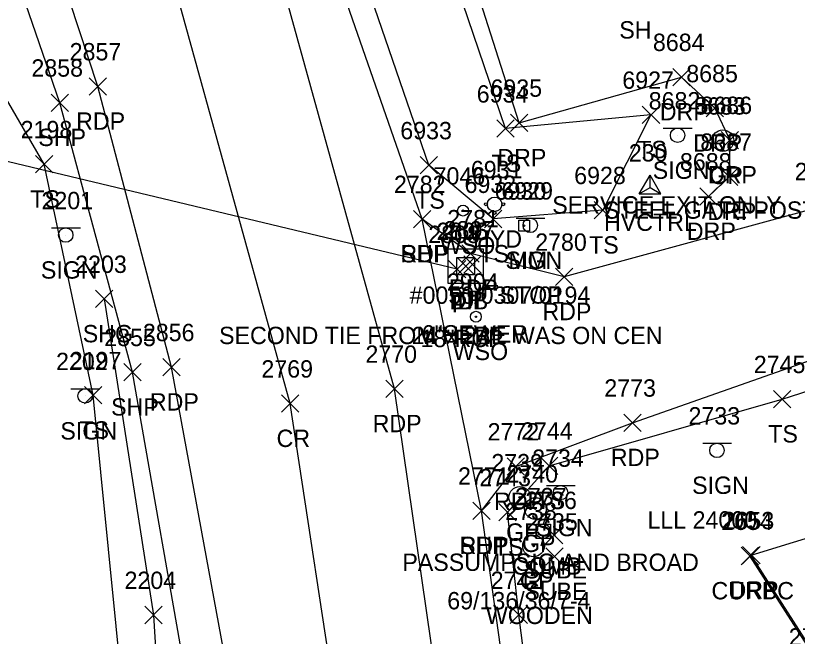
# Model space of a CAD drawing. Extents: x 1769141 to 1770911, y 735471 to 741449.
# Drawn here: x 1770593.8 to 1770683.9, y 737149.7 to 737221.2 of the extents above; entities that cross this region are included whole.
import ezdxf

# ---------------------------------------------------------------- set-up
doc = ezdxf.new("R2010")
doc.units = 0
for name, color, linetype in [('C_A', 7, 'Continuous'), ('C_I', 7, 'Continuous'), ('CPSM', 7, 'Continuous'), ('D_A', 7, 'Continuous'), ('D_C', 7, 'Continuous'), ('D_I', 7, 'Continuous'), ('D_TIC', 7, 'Continuous'), ('DCP', 7, 'Continuous'), ('DS', 7, 'Continuous'), ('L_A', 7, 'Continuous'), ('L_I', 7, 'Continuous'), ('L_TIC', 7, 'Continuous'), ('LELB', 7, 'Continuous'), ('P_A', 7, 'Continuous'), ('P_I', 7, 'Continuous'), ('P_TIC', 7, 'Continuous'), ('PET', 7, 'Continuous'), ('PRC', 7, 'Continuous'), ('PSP', 7, 'Continuous'), ('PSU', 7, 'Continuous'), ('R_A', 7, 'Continuous'), ('R_C', 7, 'Continuous'), ('R_I', 7, 'Continuous'), ('R_TIC', 7, 'Continuous'), ('RC', 7, 'Continuous'), ('RDP', 7, 'Continuous'), ('RGP', 7, 'Continuous'), ('S_A', 7, 'Continuous'), ('S_C', 7, 'Continuous'), ('S_I', 7, 'Continuous'), ('SRM', 7, 'Continuous'), ('SSGN', 7, 'Continuous'), ('U_A', 7, 'Continuous'), ('U_C', 7, 'Continuous'), ('U_I', 7, 'Continuous'), ('U_TIC', 7, 'Continuous'), ('UP', 7, 'Continuous'), ('UWFH', 7, 'Continuous'), ('UWV', 7, 'Continuous')]:
    doc.layers.add(name, color=color, linetype=linetype)

msp = doc.modelspace()

# ---------------------------------------------------------------- linework, layer by layer
at = {"layer": 'CPSM'}
for p, q in [((1770665.701, 737200.682), (1770666.951, 737202.847)), ((1770668.201, 737200.682), (1770666.951, 737202.847)), ((1770666.951, 737201.403), (1770666.951, 737202.847)), ((1770665.701, 737200.682), (1770666.951, 737201.403)), ((1770666.951, 737201.403), (1770666.951, 737201.403)), ((1770666.951, 737201.403), (1770668.201, 737200.682)), ((1770665.701, 737200.682), (1770668.201, 737200.682))]:
    msp.add_line(p, q, dxfattribs=at)
at = {"layer": 'D_TIC'}
for points in [[(1770644.731, 737191.354), (1770646.731, 737193.354)], [(1770646.731, 737191.354), (1770644.731, 737193.354)], [(1770645.493, 737191.533), (1770647.493, 737193.533)], [(1770647.493, 737191.533), (1770645.493, 737193.533)], [(1770643.721, 737191.004), (1770645.721, 737193.004)], [(1770645.721, 737191.004), (1770643.721, 737193.004)]]:
    msp.add_lwpolyline(points, dxfattribs=at)
at = {"layer": 'DCP'}
msp.add_lwpolyline([(1770644.721, 737192.004), (1770575.14, 737208.644)], dxfattribs=at)
at = {"layer": 'DS'}
for p, q in [((1770643.694, 737194.347), (1770647.694, 737194.347)), ((1770643.694, 737190.347), (1770643.694, 737194.347)), ((1770647.694, 737194.347), (1770647.694, 737190.347)), ((1770644.694, 737191.347), (1770644.694, 737193.347)), ((1770644.694, 737193.347), (1770646.694, 737193.347)), ((1770646.694, 737193.347), (1770646.694, 737191.347)), ((1770645.699, 737192.349), (1770645.699, 737192.349)), ((1770645.699, 737192.349), (1770645.699, 737192.349)), ((1770646.694, 737191.347), (1770644.694, 737191.347)), ((1770647.694, 737190.347), (1770643.694, 737190.347))]:
    msp.add_line(p, q, dxfattribs=at)
at = {"layer": 'L_TIC'}
for points in [[(1770666.059, 737208.784), (1770668.059, 737210.784)], [(1770668.059, 737208.784), (1770666.059, 737210.784)], [(1770666.059, 737208.784), (1770668.059, 737210.784)], [(1770668.059, 737208.784), (1770666.059, 737210.784)], [(1770649.276, 737207.194), (1770651.276, 737209.194)], [(1770651.276, 737207.194), (1770649.276, 737209.194)], [(1770596.087, 737203.083), (1770598.087, 737205.083)], [(1770598.087, 737203.083), (1770596.087, 737205.083)], [(1770640.464, 737202.965), (1770642.464, 737204.965)], [(1770642.464, 737202.965), (1770640.464, 737204.965)], [(1770660.511, 737197.795), (1770662.511, 737199.795)], [(1770662.511, 737197.795), (1770660.511, 737199.795)], [(1770647.869, 737196.776), (1770649.869, 737198.776)], [(1770649.869, 737196.776), (1770647.869, 737198.776)], [(1770601.747, 737176.456), (1770603.747, 737178.456)], [(1770603.747, 737176.456), (1770601.747, 737178.456)], [(1770681.17, 737176.009), (1770683.17, 737178.009)], [(1770683.17, 737176.009), (1770681.17, 737178.009)], [(1770654.338, 737168.333), (1770656.338, 737170.333)], [(1770656.338, 737168.333), (1770654.338, 737170.333)], [(1770649.53, 737162.97), (1770651.53, 737164.97)], [(1770651.53, 737162.97), (1770649.53, 737164.97)], [(1770650.841, 737151.128), (1770652.841, 737153.128)], [(1770652.841, 737151.128), (1770650.841, 737153.128)]]:
    msp.add_lwpolyline(points, dxfattribs=at)
at = {"layer": 'LELB'}
for points in [[(1770667.059, 737209.784), (1770650.276, 737208.194), (1770639.804, 737239.076), (1770626.588, 737278.985), (1770615.665, 737316.741), (1770606.889, 737344.413), (1770623.935, 737352.443), (1770627.12, 737356.412), (1770639.628, 737361.755)], [(1770667.059, 737209.784), (1770661.511, 737198.795), (1770648.869, 737197.776), (1770641.464, 737203.965), (1770629.375, 737239.096), (1770618.324, 737274.713), (1770606.199, 737314.017), (1770597.958, 737339.829), (1770601.068, 737347.648), (1770609.076, 737352.74), (1770612.603, 737353.688), (1770612.143, 737354.974), (1770623.018, 737358.017), (1770623.556, 737356.471), (1770626.216, 737360.588)], [(1770527.475, 736899.163), (1770538.393, 736913.827), (1770566.54, 736966.131), (1770583.868, 736999.5), (1770597.778, 737030.524), (1770603.735, 737066.69), (1770606.985, 737105.208), (1770606.274, 737141.963), (1770602.747, 737177.456), (1770597.087, 737204.083), (1770584.307, 737226.172)], [(1770653.31, 737140.571), (1770651.841, 737152.128), (1770650.53, 737163.97), (1770655.338, 737169.333), (1770682.17, 737177.009), (1770704.999, 737184.353), (1770726.776, 737190.276), (1770746.344, 737194.538)]]:
    msp.add_lwpolyline(points, dxfattribs=at)
at = {"layer": 'P_TIC'}
for points in [[(1770602.3, 737212.06), (1770604.3, 737214.06)], [(1770604.3, 737212.06), (1770602.3, 737214.06)], [(1770597.894, 737210.185), (1770599.894, 737212.185)], [(1770599.894, 737210.185), (1770597.894, 737212.185)], [(1770639.683, 737196.771), (1770641.683, 737198.771)], [(1770641.683, 737196.771), (1770639.683, 737198.771)], [(1770639.683, 737196.771), (1770641.683, 737198.771)], [(1770641.683, 737196.771), (1770639.683, 737198.771)], [(1770645.269, 737192.815), (1770647.269, 737194.815)], [(1770647.269, 737192.815), (1770645.269, 737194.815)], [(1770656.056, 737190.112), (1770658.056, 737192.112)], [(1770658.056, 737190.112), (1770656.056, 737192.112)], [(1770603.018, 737187.558), (1770605.018, 737189.558)], [(1770605.018, 737187.558), (1770603.018, 737189.558)], [(1770610.798, 737179.693), (1770612.798, 737181.693)], [(1770612.798, 737179.693), (1770610.798, 737181.693)], [(1770606.285, 737179.121), (1770608.285, 737181.121)], [(1770608.285, 737179.121), (1770606.285, 737181.121)], [(1770636.483, 737177.199), (1770638.483, 737179.199)], [(1770638.483, 737177.199), (1770636.483, 737179.199)], [(1770624.462, 737175.494), (1770626.462, 737177.494)], [(1770626.462, 737175.494), (1770624.462, 737177.494)], [(1770663.939, 737173.295), (1770665.939, 737175.295)], [(1770665.939, 737173.295), (1770663.939, 737175.295)], [(1770650.48, 737168.242), (1770652.48, 737170.242)], [(1770652.48, 737168.242), (1770650.48, 737170.242)], [(1770646.506, 737163.146), (1770648.506, 737165.146)], [(1770648.506, 737163.146), (1770646.506, 737165.146)], [(1770646.506, 737163.146), (1770648.506, 737165.146)], [(1770648.506, 737163.146), (1770646.506, 737165.146)], [(1770608.705, 737151.125), (1770610.705, 737153.125)], [(1770610.705, 737151.125), (1770608.705, 737153.125)]]:
    msp.add_lwpolyline(points, dxfattribs=at)
at = {"layer": 'PET'}
for points in [[(1770273.033, 736558.892), (1770311.785, 736611.417), (1770334.278, 736642.027), (1770362.146, 736677.394), (1770395.214, 736718.715), (1770421.357, 736750.436), (1770447.16, 736781.609), (1770463.211, 736800.129), (1770491.513, 736834.01), (1770534.736, 736889.691), (1770564.339, 736930.522), (1770585.978, 736965.52), (1770596.025, 736985.792), (1770612.398, 737032.331), (1770618.899, 737068.158), (1770621.164, 737108.893), (1770618.696, 737143.125), (1770611.798, 737180.693), (1770603.3, 737213.06), (1770592.485, 737245.879), (1770581.452, 737278.474)], [(1770275.701, 736500.443), (1770293.456, 736523.994), (1770308.246, 736544.527), (1770339.602, 736585.989), (1770354.041, 736607.647), (1770377.094, 736638.846), (1770405.465, 736677.522), (1770433.078, 736714.634), (1770457.829, 736747.118), (1770487.075, 736785.889), (1770511.852, 736818.72), (1770532.144, 736846.484), (1770557.142, 736879.905), (1770576.719, 736906.621), (1770599.363, 736940.91), (1770615.19, 736970.363), (1770629.485, 737005.853), (1770638.546, 737040.65), (1770643.239, 737068.348), (1770645.294, 737100.928), (1770643.286, 737138.022), (1770637.483, 737178.199), (1770623.12, 737230.101), (1770608.302, 737274.144)], [(1770741.957, 737215.362), (1770716.866, 737207.906), (1770686.9, 737199.25), (1770657.056, 737191.112), (1770646.269, 737193.815), (1770640.683, 737197.771)], [(1770647.506, 737164.146), (1770651.48, 737169.242), (1770664.939, 737174.295), (1770687.116, 737182.089), (1770711.527, 737190.661), (1770744.94, 737200.569)]]:
    msp.add_lwpolyline(points, dxfattribs=at)
at = {"layer": 'PRC'}
msp.add_lwpolyline([(1770275.213, 736520.725), (1770298.103, 736551.293), (1770321.863, 736584.275), (1770345.264, 736616.165), (1770366.92, 736646.031), (1770396.691, 736686.202), (1770425.295, 736724.734), (1770448.379, 736754.992), (1770477.139, 736793.691), (1770501.731, 736826.243), (1770522.956, 736854.301), (1770547.637, 736887.359), (1770567.264, 736914.203), (1770589.054, 736947.071), (1770604.648, 736975.905), (1770617.455, 737008.215), (1770626.945, 737043.995), (1770631.179, 737069.881), (1770632.95, 737101.223), (1770631.261, 737138.454), (1770625.462, 737176.494), (1770611.429, 737227.28), (1770596.591, 737271.455)], dxfattribs=at)
at = {"layer": 'PSP'}
for points in [[(1770309.307, 736612.498), (1770333.166, 736643.272), (1770360.374, 736678.088), (1770362.327, 736680.597), (1770393.293, 736720.827), (1770418.703, 736752.623), (1770444.15, 736783.405), (1770460.866, 736802.481), (1770489.604, 736835.53), (1770496.104, 736844.034), (1770495.661, 736846.229), (1770525.964, 736887.568), (1770531.668, 736892.213), (1770561.205, 736933.711), (1770581.742, 736967.46), (1770597.363, 737001.442), (1770607.312, 737032.413), (1770614.05, 737069.489), (1770616.453, 737108.678), (1770613.941, 737142.234), (1770607.285, 737180.121), (1770598.894, 737211.185), (1770587.449, 737244.334), (1770575.082, 737276.146)], [(1770340.145, 736567.061), (1770355.712, 736595.48), (1770384.336, 736632.07), (1770413.376, 736670.654), (1770426.21, 736690.901), (1770435.181, 736712.82), (1770460.126, 736745.306), (1770489.927, 736784.126), (1770514.631, 736816.065), (1770535.698, 736843.486), (1770560.973, 736877.108), (1770581.175, 736903.184), (1770605.599, 736937.839), (1770621.173, 736966.95), (1770635.97, 737003.978), (1770646.024, 737037.66), (1770650.838, 737066.811), (1770652.594, 737098.802), (1770650.922, 737139.651), (1770647.506, 737164.146), (1770640.683, 737197.771), (1770629.066, 737231.113), (1770614.088, 737275.469)]]:
    msp.add_lwpolyline(points, dxfattribs=at)
at = {"layer": 'PSU'}
msp.add_lwpolyline([(1770604.018, 737188.558), (1770609.705, 737152.125), (1770612.634, 737104.121), (1770611.16, 737071.425), (1770604.551, 737041.305), (1770590.598, 736996.499), (1770577.768, 736967.1), (1770561.81, 736939.257), (1770539.537, 736909.195), (1770528.411, 736894.864)], dxfattribs=at)
at = {"layer": 'R_TIC'}
for points in [[(1770669.587, 737213.141), (1770671.587, 737215.141)], [(1770671.587, 737213.141), (1770669.587, 737215.141)], [(1770673.434, 737209.537), (1770675.434, 737211.537)], [(1770675.434, 737209.537), (1770673.434, 737211.537)], [(1770650.862, 737207.862), (1770652.862, 737209.862)], [(1770652.862, 737207.862), (1770650.862, 737209.862)], [(1770675.131, 737205.879), (1770677.131, 737207.879)], [(1770677.131, 737205.879), (1770675.131, 737207.879)], [(1770675.057, 737201.641), (1770677.057, 737203.641)], [(1770677.057, 737201.641), (1770675.057, 737203.641)], [(1770672.702, 737199.369), (1770674.702, 737201.369)], [(1770674.702, 737199.369), (1770672.702, 737201.369)], [(1770677.447, 737157.927), (1770679.447, 737159.927)], [(1770679.447, 737157.927), (1770677.447, 737159.927)], [(1770677.625, 737158.009), (1770679.625, 737160.009)], [(1770679.625, 737158.009), (1770677.625, 737160.009)]]:
    msp.add_lwpolyline(points, dxfattribs=at)
at = {"layer": 'RC'}
msp.add_lwpolyline([(1770653.173, 737139.762), (1770653.711, 737137.452), (1770655.657, 737133.274), (1770657.395, 737130.834), (1770659.771, 737128.379), (1770662.606, 737126.44), (1770665.911, 737125.073), (1770669.989, 737124.148), (1770673.978, 737123.906), (1770678.231, 737124.619), (1770682.006, 737126.195), (1770684.892, 737128.002), (1770688.638, 737131.844), (1770690.645, 737135.217), (1770690.716, 737138.298), (1770689.231, 737142.159), (1770678.447, 737158.927)], dxfattribs=at)
at = {"layer": 'RDP'}
for points in [[(1770651.862, 737208.862), (1770642.081, 737239.565), (1770629.167, 737279.988), (1770617.176, 737317.21), (1770608.974, 737343.703), (1770621.898, 737347.934), (1770627.275, 737353.062), (1770640.145, 737357.787), (1770643.533, 737361.797), (1770642.151, 737367.132), (1770639.052, 737367.799), (1770622.328, 737363.576), (1770608.882, 737359.528), (1770602.841, 737355.207), (1770597.547, 737349.203), (1770594.142, 737341.772)], [(1770651.862, 737208.862), (1770670.587, 737214.141)], [(1770670.587, 737214.141), (1770674.434, 737210.537), (1770676.131, 737206.879), (1770676.057, 737202.641), (1770673.702, 737200.369)], [(1770665.886, 737124.928), (1770669.994, 737124.034), (1770673.956, 737123.824), (1770678.274, 737124.547), (1770682.028, 737126.012), (1770685.086, 737127.999), (1770688.791, 737131.848), (1770690.686, 737135.245), (1770690.957, 737138.391), (1770689.316, 737142.302), (1770678.625, 737159.009), (1770697.636, 737164.852), (1770726.009, 737173.895), (1770752.245, 737179.574)]]:
    msp.add_lwpolyline(points, dxfattribs=at)
at = {"layer": 'RGP'}
for p, q in [((1770675.342, 737206.806), (1770675.342, 737206.806)), ((1770651.924, 737165.688), (1770651.924, 737165.688)), ((1770653.743, 737164.389), (1770653.743, 737164.389)), ((1770653.517, 737160.083), (1770653.517, 737160.083))]:
    msp.add_line(p, q, dxfattribs=at)
for centre, radius in [((1770675.342, 737206.806), 1.25), ((1770675.342, 737206.806), 0.0833), ((1770651.924, 737165.688), 1.25), ((1770651.924, 737165.688), 0.0833), ((1770653.743, 737164.389), 1.25), ((1770653.743, 737164.389), 0.0833), ((1770653.517, 737160.083), 1.25), ((1770653.517, 737160.083), 0.0833)]:
    msp.add_circle(centre, radius, dxfattribs=at)
at = {"layer": 'SRM'}
msp.add_lwpolyline([(1770651.809, 737197.626), (1770653.059, 737197.626), (1770653.059, 737196.376), (1770651.809, 737196.376)], close=True, dxfattribs=at)
msp.add_circle((1770652.434, 737197.001), 0.0833, dxfattribs=at)
at = {"layer": 'SSGN'}
for p, q in [((1770668.475, 737208.257), (1770671.809, 737208.257)), ((1770670.122, 737207.424), (1770670.122, 737207.424)), ((1770651.499, 737197.873), (1770654.832, 737197.873)), ((1770653.145, 737197.039), (1770653.145, 737197.039)), ((1770597.94, 737196.756), (1770601.273, 737196.756)), ((1770599.587, 737195.922), (1770599.587, 737195.922)), ((1770600.186, 737178.208), (1770603.519, 737178.208)), ((1770601.833, 737177.375), (1770601.833, 737177.375)), ((1770673.016, 737171.938), (1770676.349, 737171.938)), ((1770674.663, 737171.105), (1770674.663, 737171.105)), ((1770654.994, 737167.06), (1770658.328, 737167.06)), ((1770656.641, 737166.227), (1770656.641, 737166.227))]:
    msp.add_line(p, q, dxfattribs=at)
for centre in [(1770670.122, 737207.424), (1770653.145, 737197.039), (1770599.587, 737195.922), (1770601.833, 737177.375), (1770674.663, 737171.105), (1770656.641, 737166.227)]:
    msp.add_circle(centre, 0.833, dxfattribs=at)
at = {"layer": 'U_TIC'}
for points in [[(1770654.878, 737160.341), (1770656.878, 737162.341)], [(1770656.878, 737160.341), (1770654.878, 737162.341)], [(1770654.926, 737157.858), (1770656.926, 737159.858)], [(1770656.926, 737157.858), (1770654.926, 737159.858)]]:
    msp.add_lwpolyline(points, dxfattribs=at)
at = {"layer": 'UP'}
for p, q in [((1770654.892, 737163.444), (1770654.642, 737162.61)), ((1770653.809, 737160.944), (1770653.809, 737162.61)), ((1770653.809, 737162.61), (1770655.475, 737162.61)), ((1770655.475, 737162.61), (1770655.475, 737160.944)), ((1770654.642, 737161.777), (1770654.642, 737161.777)), ((1770655.475, 737160.944), (1770653.809, 737160.944)), ((1770654.392, 737160.11), (1770654.642, 737160.944))]:
    msp.add_line(p, q, dxfattribs=at)
msp.add_circle((1770654.642, 737161.777), 0.833, dxfattribs=at)
at = {"layer": 'UWFH'}
msp.add_line((1770649.027, 737199.474), (1770649.027, 737199.474), dxfattribs=at)
for centre, radius in [((1770648.027, 737199.474), 0.167), ((1770649.027, 737199.474), 0.833), ((1770650.027, 737199.474), 0.167), ((1770649.027, 737198.474), 0.167)]:
    msp.add_circle(centre, radius, dxfattribs=at)
at = {"layer": 'UWV'}
for centre, radius in [((1770645.392, 737198.739), 0.625), ((1770645.392, 737198.739), 0.0833), ((1770646.874, 737186.51), 0.625), ((1770646.874, 737186.51), 0.0833)]:
    msp.add_circle(centre, radius, dxfattribs=at)

# ---------------------------------------------------------------- texts
at = {"layer": 'C_A'}
msp.add_text('HVCTRL', height=2, dxfattribs=at).set_placement((1770661.644, 737196.403))
at = {"layer": 'C_I'}
msp.add_text('230', height=2, dxfattribs=at).set_placement((1770664.502, 737204.403))
at = {"layer": 'D_A'}
for s, p in [('DIB', (1770643.834, 737187.354)), ('P', (1770644.099, 737187.004)), ('DI', (1770644.754, 737187.349)), ('P', (1770645.871, 737187.533))]:
    msp.add_text(s, height=2, dxfattribs=at).set_placement(p)
at = {"layer": 'D_C'}
for s, p in [('SECOND TIE FROM HERE WAS ON CEN', (1770617.267, 737183.354)), ('24"x 24"', (1770639.479, 737183.349)), ('6"SEWER', (1770640.627, 737183.533)), ('18"RCP', (1770640.493, 737183.004))]:
    msp.add_text(s, height=2, dxfattribs=at).set_placement(p)
at = {"layer": 'D_I'}
for s, p in [('2808', (1770641.383, 737195.004)), ('2806', (1770642.338, 737195.354)), ('2805', (1770642.361, 737195.349)), ('2807', (1770643.155, 737195.533))]:
    msp.add_text(s, height=2, dxfattribs=at).set_placement(p)
at = {"layer": 'L_A'}
for s, p in [('SH', (1770663.404, 737218.578)), ('TS', (1770665.468, 737204.784)), ('TS', (1770665.468, 737204.784)), ('TS', (1770648.685, 737203.194)), ('TS', (1770595.496, 737199.083)), ('TS', (1770639.874, 737198.965)), ('TS', (1770659.921, 737193.795)), ('TS', (1770647.279, 737192.776)), ('TS', (1770601.156, 737172.456)), ('TS', (1770680.579, 737172.009)), ('TS', (1770653.748, 737164.333)), ('TS', (1770648.94, 737158.97))]:
    msp.add_text(s, height=2, dxfattribs=at).set_placement(p)
at = {"layer": 'L_I'}
for s, p in [('6927', (1770663.752, 737212.784)), ('6927', (1770663.752, 737212.784)), ('6934', (1770646.969, 737211.194)), ('2198', (1770594.394, 737207.083)), ('6933', (1770638.157, 737206.965)), ('6928', (1770658.204, 737201.795)), ('6932', (1770645.562, 737200.776)), ('2197', (1770600.054, 737180.456)), ('2745', (1770678.91, 737180.009)), ('2744', (1770652.079, 737172.333)), ('2743', (1770647.27, 737166.97)), ('2742', (1770648.582, 737155.128)), ('2730', (1770682.943, 737148.599))]:
    msp.add_text(s, height=2, dxfattribs=at).set_placement(p)
at = {"layer": 'P_A'}
for s, p in [('RDP', (1770600.788, 737208.06)), ('SHP', (1770596.429, 737206.185)), ('SHP', (1770638.219, 737192.771)), ('RDP', (1770638.171, 737192.771)), ('RDP', (1770643.757, 737188.815)), ('RDP', (1770654.544, 737186.112)), ('SHG', (1770601.553, 737183.558)), ('SHP', (1770604.821, 737175.121)), ('RDP', (1770609.286, 737175.693)), ('RDP', (1770634.971, 737173.199)), ('CR', (1770623.895, 737171.494)), ('RDP', (1770662.428, 737169.295)), ('RDP', (1770648.968, 737164.242)), ('SHP', (1770645.042, 737159.146)), ('RDP', (1770644.994, 737159.146))]:
    msp.add_text(s, height=2, dxfattribs=at).set_placement(p)
at = {"layer": 'P_I'}
for s, p in [('2857', (1770600.04, 737216.06)), ('2858', (1770595.634, 737214.185)), ('2779', (1770683.632, 737202.25)), ('2782', (1770637.423, 737200.771)), ('2782', (1770637.423, 737200.771)), ('2781', (1770643.576, 737196.815)), ('2780', (1770653.709, 737194.112)), ('2203', (1770600.679, 737191.558)), ('2855', (1770604.026, 737183.121)), ('2856', (1770608.483, 737183.693)), ('2770', (1770634.137, 737181.199)), ('2769', (1770622.147, 737179.494)), ('2773', (1770661.679, 737177.295)), ('2772', (1770648.22, 737172.242)), ('2771', (1770644.813, 737167.146)), ('2771', (1770644.813, 737167.146)), ('2204', (1770606.366, 737155.125))]:
    msp.add_text(s, height=2, dxfattribs=at).set_placement(p)
at = {"layer": 'R_A'}
for s, p in [('DRP', (1770668.075, 737209.141)), ('DRP', (1770671.922, 737205.537)), ('DRP', (1770649.35, 737203.862)), ('DRP', (1770673.619, 737201.879)), ('GP', (1770673.775, 737201.806)), ('DRP', (1770673.546, 737197.641)), ('DRP', (1770671.19, 737195.369)), ('GP', (1770650.357, 737160.688)), ('GP', (1770652.176, 737159.389)), ('GP', (1770651.95, 737155.083)), ('CURBC', (1770674.03, 737153.927)), ('DRP', (1770676.113, 737154.009))]:
    msp.add_text(s, height=2, dxfattribs=at).set_placement(p)
at = {"layer": 'R_C'}
for s, p in [('STEEL GATE POST', (1770661.617, 737197.806)), ('WOODEN', (1770648.029, 737151.083))]:
    msp.add_text(s, height=2, dxfattribs=at).set_placement(p)
at = {"layer": 'R_I'}
for s, p in [('8684', (1770667.28, 737217.141)), ('8685', (1770671.127, 737213.537)), ('6935', (1770648.555, 737211.862)), ('8683', (1770672.035, 737209.806)), ('8686', (1770672.769, 737209.879)), ('8687', (1770672.75, 737205.641)), ('8688', (1770670.395, 737203.369)), ('2739', (1770648.656, 737168.688)), ('2740', (1770650.396, 737167.389)), ('2738', (1770650.257, 737163.083)), ('2654', (1770675.14, 737161.927)), ('2653', (1770675.318, 737162.009))]:
    msp.add_text(s, height=2, dxfattribs=at).set_placement(p)
at = {"layer": 'S_A'}
for s, p in [('SIGN', (1770667.26, 737202.404)), ('SIGN', (1770650.283, 737192.019)), ('MM', (1770650.623, 737192.001)), ('SIGN', (1770596.725, 737190.902)), ('SIGN', (1770598.971, 737172.355)), ('SIGN', (1770671.801, 737166.085)), ('SIGN', (1770653.779, 737161.207))]:
    msp.add_text(s, height=2, dxfattribs=at).set_placement(p)
at = {"layer": 'S_C'}
for s, p in [('SERVICE EXIT ONLY', (1770655.677, 737198.404)), ('#0050/0307/0194', (1770639.238, 737188.001)), ('STOP', (1770649.606, 737188.019)), ('LLL 24000', (1770666.651, 737162.085)), ('PASSUMPSIC AND BROAD', (1770638.393, 737157.207))]:
    msp.add_text(s, height=2, dxfattribs=at).set_placement(p)
at = {"layer": 'S_I'}
for s, p in [('8682', (1770666.795, 737210.404)), ('6930', (1770649.041, 737200.001)), ('6929', (1770649.811, 737200.019)), ('2201', (1770596.796, 737198.902)), ('2202', (1770598.475, 737180.355)), ('2733', (1770671.383, 737174.085)), ('2734', (1770653.362, 737169.207))]:
    msp.add_text(s, height=2, dxfattribs=at).set_placement(p)
at = {"layer": 'U_A'}
for s, p in [('HYD', (1770646.547, 737194.474)), ('WSO', (1770642.722, 737193.739)), ('WSO', (1770644.205, 737181.51)), ('COMB', (1770651.028, 737156.777)), ('SUBE', (1770652.413, 737156.341)), ('SUBE', (1770652.461, 737153.858))]:
    msp.add_text(s, height=2, dxfattribs=at).set_placement(p)
at = {"layer": 'U_C'}
msp.add_text('69/136/36/7-4', height=2, dxfattribs=at).set_placement((1770643.571, 737152.777))
at = {"layer": 'U_I'}
for s, p in [('6931', (1770646.287, 737202.474)), ('7046', (1770641.998, 737201.739)), ('2904', (1770643.535, 737189.51)), ('2737', (1770651.382, 737164.777)), ('2736', (1770652.563, 737164.341)), ('2735', (1770652.666, 737161.858))]:
    msp.add_text(s, height=2, dxfattribs=at).set_placement(p)

doc.saveas('drawing.dxf')
